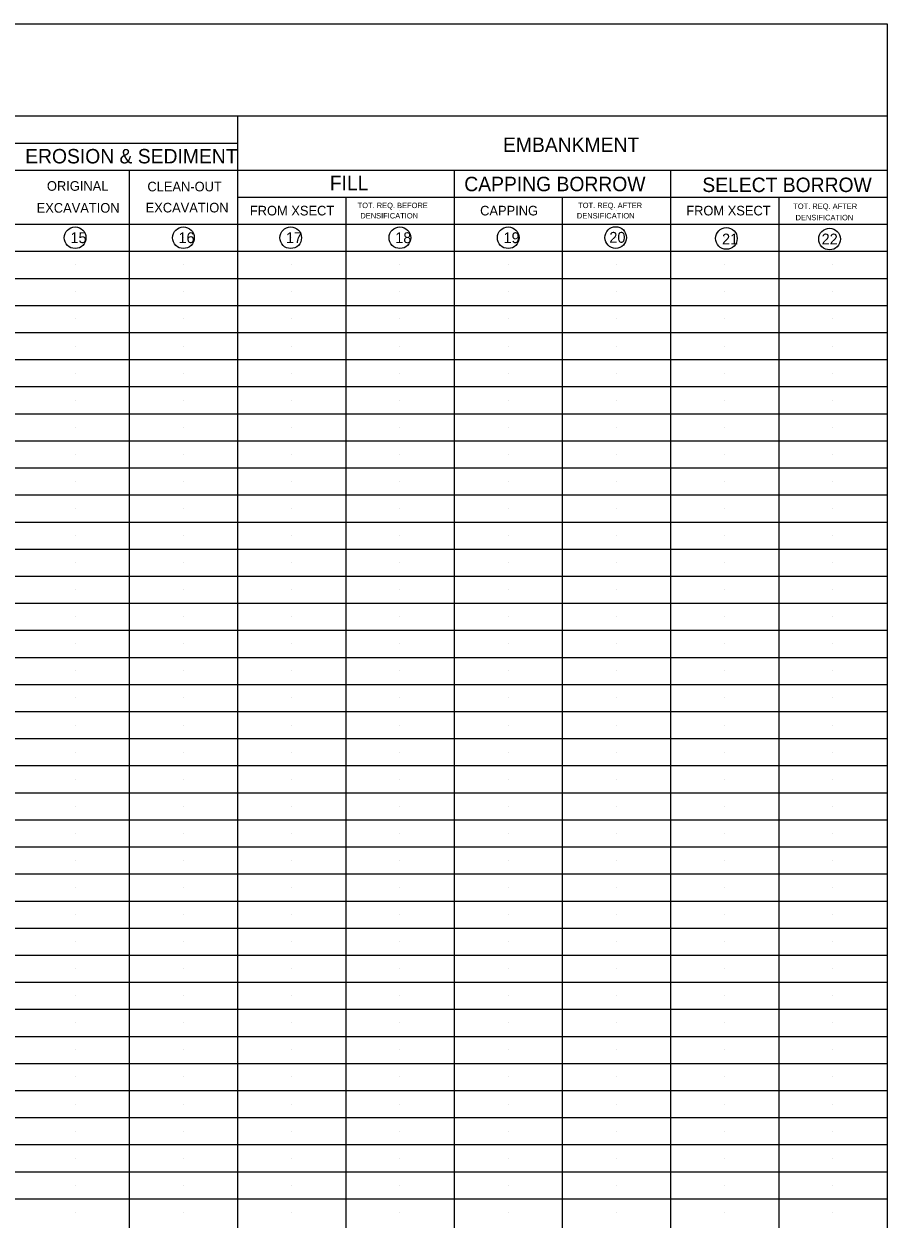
# Model space of a CAD drawing. Extents: x 1.3 to 38.6, y 0 to 21.1.
# Drawn here: x 15.32 to 22.5, y 11.12 to 21.05 of the extents above; entities that cross this region are included whole.
import ezdxf

# ---------------------------------------------------------------- set-up
doc = ezdxf.new("R2010")
doc.units = 0
for name, color, linetype in [('CONS-LOGO', 7, 'Continuous'), ('TTLB-TEXT', 7, 'Continuous'), ('USER-LINE', 7, 'Continuous')]:
    doc.layers.add(name, color=color, linetype=linetype)

msp = doc.modelspace()

# ---------------------------------------------------------------- linework, layer by layer
at = {"layer": 'CONS-LOGO'}
for centre in [(15.7479, 19.278), (16.6479, 19.278), (17.5398, 19.278), (18.4479, 19.278), (19.3479, 19.278), (20.2416, 19.2789), (21.1619, 19.272), (22.02, 19.267)]:
    msp.add_circle(centre, 0.09, dxfattribs=at)
at = {"layer": 'TTLB-TEXT'}
for p, q in [((2.248, 21.055), (22.498, 21.055)), ((22.498, 21.055), (22.498, 1.165)), ((2.248, 20.29), (22.498, 20.29)), ((17.098, 20.2901), (17.098, 4.54)), ((2.698, 20.065), (17.098, 20.065)), ((2.698, 19.84), (22.498, 19.84)), ((16.198, 19.8401), (16.198, 4.54)), ((18.898, 19.84), (18.898, 4.54)), ((20.698, 19.84), (20.698, 4.54)), ((17.098, 19.615), (22.498, 19.615)), ((17.998, 19.6151), (17.998, 4.54)), ((19.798, 19.6151), (19.798, 4.54)), ((21.598, 19.615), (21.598, 1.165)), ((2.698, 19.39), (22.498, 19.39)), ((2.248, 19.165), (22.498, 19.165)), ((2.698, 18.94), (22.498, 18.94)), ((2.698, 18.715), (22.498, 18.715)), ((2.698, 18.49), (22.498, 18.49)), ((2.698, 18.265), (22.498, 18.265)), ((2.698, 18.04), (22.498, 18.04)), ((2.698, 17.815), (22.498, 17.815)), ((2.698, 17.59), (22.498, 17.59)), ((2.698, 17.365), (22.498, 17.365)), ((2.698, 17.14), (22.498, 17.14)), ((2.698, 16.915), (22.498, 16.915)), ((2.698, 16.69), (22.498, 16.69)), ((2.698, 16.465), (22.498, 16.465)), ((2.698, 16.24), (22.498, 16.24)), ((2.698, 16.015), (22.498, 16.015)), ((2.698, 15.79), (22.498, 15.79)), ((2.698, 15.565), (22.498, 15.565)), ((2.698, 15.34), (22.498, 15.34)), ((2.698, 15.115), (22.498, 15.115)), ((2.698, 14.89), (22.498, 14.89)), ((2.698, 14.665), (22.498, 14.665)), ((2.698, 14.44), (22.498, 14.44)), ((2.698, 14.215), (22.498, 14.215)), ((2.698, 13.99), (22.498, 13.99)), ((2.698, 13.765), (22.498, 13.765)), ((2.698, 13.54), (22.498, 13.54)), ((2.698, 13.315), (22.498, 13.315)), ((2.698, 13.09), (22.498, 13.09)), ((2.698, 12.865), (22.498, 12.865)), ((2.698, 12.64), (22.498, 12.64)), ((2.698, 12.415), (22.498, 12.415)), ((2.698, 12.19), (22.498, 12.19)), ((2.698, 11.965), (22.498, 11.965)), ((2.698, 11.74), (22.498, 11.74)), ((2.698, 11.515), (22.498, 11.515)), ((2.698, 11.29), (22.498, 11.29))]:
    msp.add_line(p, q, dxfattribs=at)
at = {"layer": 'USER-LINE'}
for p, q in [((17.548, 19.5025), (17.548, 19.5025)), ((18.448, 19.5025), (18.448, 19.5025)), ((19.348, 19.5025), (19.348, 19.5025)), ((20.248, 19.5025), (20.248, 19.5025)), ((21.148, 19.5025), (21.148, 19.5025)), ((22.048, 19.5025), (22.048, 19.5025)), ((15.748, 19.2775), (15.748, 19.2775)), ((16.648, 19.2775), (16.648, 19.2775)), ((17.548, 19.2775), (17.548, 19.2775)), ((18.448, 19.2775), (18.448, 19.2775)), ((19.348, 19.2775), (19.348, 19.2775)), ((20.248, 19.2775), (20.248, 19.2775)), ((21.148, 19.2775), (21.148, 19.2775)), ((22.048, 19.2775), (22.048, 19.2775)), ((15.748, 19.0525), (15.748, 19.0525)), ((16.648, 19.0525), (16.648, 19.0525)), ((17.548, 19.0525), (17.548, 19.0525)), ((18.448, 19.0525), (18.448, 19.0525)), ((19.348, 19.0525), (19.348, 19.0525)), ((20.248, 19.0525), (20.248, 19.0525)), ((21.148, 19.0525), (21.148, 19.0525)), ((22.048, 19.0525), (22.048, 19.0525)), ((15.748, 18.8275), (15.748, 18.8275)), ((16.648, 18.8275), (16.648, 18.8275)), ((17.548, 18.8275), (17.548, 18.8275)), ((18.448, 18.8275), (18.448, 18.8275)), ((19.348, 18.8275), (19.348, 18.8275)), ((20.248, 18.8275), (20.248, 18.8275)), ((21.148, 18.8275), (21.148, 18.8275)), ((22.048, 18.8275), (22.048, 18.8275)), ((15.748, 18.6025), (15.748, 18.6025)), ((16.648, 18.6025), (16.648, 18.6025)), ((17.548, 18.6025), (17.548, 18.6025)), ((18.448, 18.6025), (18.448, 18.6025)), ((19.348, 18.6025), (19.348, 18.6025)), ((20.248, 18.6025), (20.248, 18.6025)), ((21.148, 18.6025), (21.148, 18.6025)), ((22.048, 18.6025), (22.048, 18.6025)), ((15.748, 18.3775), (15.748, 18.3775)), ((16.648, 18.3775), (16.648, 18.3775)), ((17.548, 18.3775), (17.548, 18.3775)), ((18.448, 18.3775), (18.448, 18.3775)), ((19.348, 18.3775), (19.348, 18.3775)), ((20.248, 18.3775), (20.248, 18.3775)), ((21.148, 18.3775), (21.148, 18.3775)), ((22.048, 18.3775), (22.048, 18.3775)), ((15.748, 18.1525), (15.748, 18.1525)), ((16.648, 18.1525), (16.648, 18.1525)), ((17.548, 18.1525), (17.548, 18.1525)), ((18.448, 18.1525), (18.448, 18.1525)), ((19.348, 18.1525), (19.348, 18.1525)), ((20.248, 18.1525), (20.248, 18.1525)), ((21.148, 18.1525), (21.148, 18.1525)), ((22.048, 18.1525), (22.048, 18.1525)), ((15.748, 17.9275), (15.748, 17.9275)), ((16.648, 17.9275), (16.648, 17.9275)), ((17.548, 17.9275), (17.548, 17.9275)), ((18.448, 17.9275), (18.448, 17.9275)), ((19.348, 17.9275), (19.348, 17.9275)), ((20.248, 17.9275), (20.248, 17.9275)), ((21.148, 17.9275), (21.148, 17.9275)), ((22.048, 17.9275), (22.048, 17.9275)), ((15.748, 17.7025), (15.748, 17.7025)), ((16.648, 17.7025), (16.648, 17.7025)), ((17.548, 17.7025), (17.548, 17.7025)), ((18.448, 17.7025), (18.448, 17.7025)), ((19.348, 17.7025), (19.348, 17.7025)), ((20.248, 17.7025), (20.248, 17.7025)), ((21.148, 17.7025), (21.148, 17.7025)), ((22.048, 17.7025), (22.048, 17.7025)), ((15.748, 17.4775), (15.748, 17.4775)), ((16.648, 17.4775), (16.648, 17.4775)), ((17.548, 17.4775), (17.548, 17.4775)), ((18.448, 17.4775), (18.448, 17.4775)), ((19.348, 17.4775), (19.348, 17.4775)), ((20.248, 17.4775), (20.248, 17.4775)), ((21.148, 17.4775), (21.148, 17.4775)), ((22.048, 17.4775), (22.048, 17.4775)), ((15.748, 17.2525), (15.748, 17.2525)), ((16.648, 17.2525), (16.648, 17.2525)), ((17.548, 17.2525), (17.548, 17.2525)), ((18.448, 17.2525), (18.448, 17.2525)), ((19.348, 17.2525), (19.348, 17.2525)), ((20.248, 17.2525), (20.248, 17.2525)), ((21.148, 17.2525), (21.148, 17.2525)), ((22.048, 17.2525), (22.048, 17.2525)), ((15.748, 17.0275), (15.748, 17.0275)), ((16.648, 17.0275), (16.648, 17.0275)), ((17.548, 17.0275), (17.548, 17.0275)), ((18.448, 17.0275), (18.448, 17.0275)), ((19.348, 17.0275), (19.348, 17.0275)), ((20.248, 17.0275), (20.248, 17.0275)), ((21.148, 17.0275), (21.148, 17.0275)), ((22.048, 17.0275), (22.048, 17.0275)), ((15.748, 16.8025), (15.748, 16.8025)), ((16.648, 16.8025), (16.648, 16.8025)), ((17.548, 16.8025), (17.548, 16.8025)), ((18.448, 16.8025), (18.448, 16.8025)), ((19.348, 16.8025), (19.348, 16.8025)), ((20.248, 16.8025), (20.248, 16.8025)), ((21.148, 16.8025), (21.148, 16.8025)), ((22.048, 16.8025), (22.048, 16.8025)), ((15.748, 16.5775), (15.748, 16.5775)), ((16.648, 16.5775), (16.648, 16.5775)), ((17.548, 16.5775), (17.548, 16.5775)), ((18.448, 16.5775), (18.448, 16.5775)), ((19.348, 16.5775), (19.348, 16.5775)), ((20.248, 16.5775), (20.248, 16.5775)), ((21.148, 16.5775), (21.148, 16.5775)), ((22.048, 16.5775), (22.048, 16.5775)), ((15.748, 16.3525), (15.748, 16.3525)), ((16.648, 16.3525), (16.648, 16.3525)), ((17.548, 16.3525), (17.548, 16.3525)), ((18.448, 16.3525), (18.448, 16.3525)), ((19.348, 16.3525), (19.348, 16.3525)), ((20.248, 16.3525), (20.248, 16.3525)), ((21.148, 16.3525), (21.148, 16.3525)), ((22.048, 16.3525), (22.048, 16.3525)), ((15.748, 16.1275), (15.748, 16.1275)), ((16.648, 16.1275), (16.648, 16.1275)), ((17.548, 16.1275), (17.548, 16.1275)), ((18.448, 16.1275), (18.448, 16.1275)), ((19.348, 16.1275), (19.348, 16.1275)), ((20.248, 16.1275), (20.248, 16.1275)), ((21.148, 16.1275), (21.148, 16.1275)), ((22.048, 16.1275), (22.048, 16.1275)), ((15.748, 15.9025), (15.748, 15.9025)), ((16.648, 15.9025), (16.648, 15.9025)), ((17.548, 15.9025), (17.548, 15.9025)), ((18.448, 15.9025), (18.448, 15.9025)), ((19.348, 15.9025), (19.348, 15.9025)), ((20.248, 15.9025), (20.248, 15.9025)), ((21.148, 15.9025), (21.148, 15.9025)), ((22.048, 15.9025), (22.048, 15.9025)), ((15.748, 15.6775), (15.748, 15.6775)), ((16.648, 15.6775), (16.648, 15.6775)), ((17.548, 15.6775), (17.548, 15.6775)), ((18.448, 15.6775), (18.448, 15.6775)), ((19.348, 15.6775), (19.348, 15.6775)), ((20.248, 15.6775), (20.248, 15.6775)), ((21.148, 15.6775), (21.148, 15.6775)), ((22.048, 15.6775), (22.048, 15.6775)), ((15.748, 15.4525), (15.748, 15.4525)), ((16.648, 15.4525), (16.648, 15.4525)), ((17.548, 15.4525), (17.548, 15.4525)), ((18.448, 15.4525), (18.448, 15.4525)), ((19.348, 15.4525), (19.348, 15.4525)), ((20.248, 15.4525), (20.248, 15.4525)), ((21.148, 15.4525), (21.148, 15.4525)), ((22.048, 15.4525), (22.048, 15.4525)), ((15.748, 15.2275), (15.748, 15.2275)), ((16.648, 15.2275), (16.648, 15.2275)), ((17.548, 15.2275), (17.548, 15.2275)), ((18.448, 15.2275), (18.448, 15.2275)), ((19.348, 15.2275), (19.348, 15.2275)), ((20.248, 15.2275), (20.248, 15.2275)), ((21.148, 15.2275), (21.148, 15.2275)), ((22.048, 15.2275), (22.048, 15.2275)), ((15.748, 15.0025), (15.748, 15.0025)), ((16.648, 15.0025), (16.648, 15.0025)), ((17.548, 15.0025), (17.548, 15.0025)), ((18.448, 15.0025), (18.448, 15.0025)), ((19.348, 15.0025), (19.348, 15.0025)), ((20.248, 15.0025), (20.248, 15.0025)), ((21.148, 15.0025), (21.148, 15.0025)), ((22.048, 15.0025), (22.048, 15.0025)), ((15.748, 14.7775), (15.748, 14.7775)), ((16.648, 14.7775), (16.648, 14.7775)), ((17.548, 14.7775), (17.548, 14.7775)), ((18.448, 14.7775), (18.448, 14.7775)), ((19.348, 14.7775), (19.348, 14.7775)), ((20.248, 14.7775), (20.248, 14.7775)), ((21.148, 14.7775), (21.148, 14.7775)), ((22.048, 14.7775), (22.048, 14.7775)), ((15.748, 14.5525), (15.748, 14.5525)), ((16.648, 14.5525), (16.648, 14.5525)), ((17.548, 14.5525), (17.548, 14.5525)), ((18.448, 14.5525), (18.448, 14.5525)), ((19.348, 14.5525), (19.348, 14.5525)), ((20.248, 14.5525), (20.248, 14.5525)), ((21.148, 14.5525), (21.148, 14.5525)), ((22.048, 14.5525), (22.048, 14.5525)), ((15.748, 14.3275), (15.748, 14.3275)), ((16.648, 14.3275), (16.648, 14.3275)), ((17.548, 14.3275), (17.548, 14.3275)), ((18.448, 14.3275), (18.448, 14.3275)), ((19.348, 14.3275), (19.348, 14.3275)), ((20.248, 14.3275), (20.248, 14.3275)), ((21.148, 14.3275), (21.148, 14.3275)), ((22.048, 14.3275), (22.048, 14.3275)), ((15.748, 14.1025), (15.748, 14.1025)), ((16.648, 14.1025), (16.648, 14.1025)), ((17.548, 14.1025), (17.548, 14.1025)), ((18.448, 14.1025), (18.448, 14.1025)), ((19.348, 14.1025), (19.348, 14.1025)), ((20.248, 14.1025), (20.248, 14.1025)), ((21.148, 14.1025), (21.148, 14.1025)), ((22.048, 14.1025), (22.048, 14.1025)), ((15.748, 13.8775), (15.748, 13.8775)), ((16.648, 13.8775), (16.648, 13.8775)), ((17.548, 13.8775), (17.548, 13.8775)), ((18.448, 13.8775), (18.448, 13.8775)), ((19.348, 13.8775), (19.348, 13.8775)), ((20.248, 13.8775), (20.248, 13.8775)), ((21.148, 13.8775), (21.148, 13.8775)), ((22.048, 13.8775), (22.048, 13.8775)), ((15.748, 13.6525), (15.748, 13.6525)), ((16.648, 13.6525), (16.648, 13.6525)), ((17.548, 13.6525), (17.548, 13.6525)), ((18.448, 13.6525), (18.448, 13.6525)), ((19.348, 13.6525), (19.348, 13.6525)), ((20.248, 13.6525), (20.248, 13.6525)), ((21.148, 13.6525), (21.148, 13.6525)), ((22.048, 13.6525), (22.048, 13.6525)), ((15.748, 13.4275), (15.748, 13.4275)), ((16.648, 13.4275), (16.648, 13.4275)), ((17.548, 13.4275), (17.548, 13.4275)), ((18.448, 13.4275), (18.448, 13.4275)), ((19.348, 13.4275), (19.348, 13.4275)), ((20.248, 13.4275), (20.248, 13.4275)), ((21.148, 13.4275), (21.148, 13.4275)), ((22.048, 13.4275), (22.048, 13.4275)), ((15.748, 13.2025), (15.748, 13.2025)), ((16.648, 13.2025), (16.648, 13.2025)), ((17.548, 13.2025), (17.548, 13.2025)), ((18.448, 13.2025), (18.448, 13.2025)), ((19.348, 13.2025), (19.348, 13.2025)), ((20.248, 13.2025), (20.248, 13.2025)), ((21.148, 13.2025), (21.148, 13.2025)), ((22.048, 13.2025), (22.048, 13.2025)), ((15.748, 12.9775), (15.748, 12.9775)), ((16.648, 12.9775), (16.648, 12.9775)), ((17.548, 12.9775), (17.548, 12.9775)), ((18.448, 12.9775), (18.448, 12.9775)), ((19.348, 12.9775), (19.348, 12.9775)), ((20.248, 12.9775), (20.248, 12.9775)), ((21.148, 12.9775), (21.148, 12.9775)), ((22.048, 12.9775), (22.048, 12.9775)), ((15.748, 12.7525), (15.748, 12.7525)), ((16.648, 12.7525), (16.648, 12.7525)), ((17.548, 12.7525), (17.548, 12.7525)), ((18.448, 12.7525), (18.448, 12.7525)), ((19.348, 12.7525), (19.348, 12.7525)), ((20.248, 12.7525), (20.248, 12.7525)), ((21.148, 12.7525), (21.148, 12.7525)), ((22.048, 12.7525), (22.048, 12.7525)), ((15.748, 12.5275), (15.748, 12.5275)), ((16.648, 12.5275), (16.648, 12.5275)), ((17.548, 12.5275), (17.548, 12.5275)), ((18.448, 12.5275), (18.448, 12.5275)), ((19.348, 12.5275), (19.348, 12.5275)), ((20.248, 12.5275), (20.248, 12.5275)), ((21.148, 12.5275), (21.148, 12.5275)), ((22.048, 12.5275), (22.048, 12.5275)), ((15.748, 12.3025), (15.748, 12.3025)), ((16.648, 12.3025), (16.648, 12.3025)), ((17.548, 12.3025), (17.548, 12.3025)), ((18.448, 12.3025), (18.448, 12.3025)), ((19.348, 12.3025), (19.348, 12.3025)), ((20.248, 12.3025), (20.248, 12.3025)), ((21.148, 12.3025), (21.148, 12.3025)), ((22.048, 12.3025), (22.048, 12.3025)), ((15.748, 12.0775), (15.748, 12.0775)), ((16.648, 12.0775), (16.648, 12.0775)), ((17.548, 12.0775), (17.548, 12.0775)), ((18.448, 12.0775), (18.448, 12.0775)), ((19.348, 12.0775), (19.348, 12.0775)), ((20.248, 12.0775), (20.248, 12.0775)), ((21.148, 12.0775), (21.148, 12.0775)), ((22.048, 12.0775), (22.048, 12.0775)), ((15.748, 11.8525), (15.748, 11.8525)), ((16.648, 11.8525), (16.648, 11.8525)), ((17.548, 11.8525), (17.548, 11.8525)), ((18.448, 11.8525), (18.448, 11.8525)), ((19.348, 11.8525), (19.348, 11.8525)), ((20.248, 11.8525), (20.248, 11.8525)), ((21.148, 11.8525), (21.148, 11.8525)), ((22.048, 11.8525), (22.048, 11.8525)), ((15.748, 11.6275), (15.748, 11.6275)), ((16.648, 11.6275), (16.648, 11.6275)), ((17.548, 11.6275), (17.548, 11.6275)), ((18.448, 11.6275), (18.448, 11.6275)), ((19.348, 11.6275), (19.348, 11.6275)), ((20.248, 11.6275), (20.248, 11.6275)), ((21.148, 11.6275), (21.148, 11.6275)), ((22.048, 11.6275), (22.048, 11.6275)), ((15.748, 11.4025), (15.748, 11.4025)), ((16.648, 11.4025), (16.648, 11.4025)), ((17.548, 11.4025), (17.548, 11.4025)), ((18.448, 11.4025), (18.448, 11.4025)), ((19.348, 11.4025), (19.348, 11.4025)), ((20.248, 11.4025), (20.248, 11.4025)), ((21.148, 11.4025), (21.148, 11.4025)), ((22.048, 11.4025), (22.048, 11.4025)), ((15.748, 11.1775), (15.748, 11.1775)), ((16.648, 11.1775), (16.648, 11.1775)), ((17.548, 11.1775), (17.548, 11.1775)), ((18.448, 11.1775), (18.448, 11.1775)), ((19.348, 11.1775), (19.348, 11.1775)), ((20.248, 11.1775), (20.248, 11.1775)), ((21.148, 11.1775), (21.148, 11.1775)), ((22.048, 11.1775), (22.048, 11.1775))]:
    msp.add_line(p, q, dxfattribs=at)

# ---------------------------------------------------------------- texts
at = {"layer": 'CONS-LOGO'}
for s, height, p in [('EMBANKMENT', 0.12, (19.3051, 19.9905)), ('EROSION & SEDIMENT', 0.12, (15.3324, 19.8955)), ('FILL', 0.12, (17.8648, 19.6725)), ('CAPPING BORROW', 0.12, (18.9828, 19.6645)), ('SELECT BORROW', 0.12, (20.9618, 19.6575)), ('ORIGINAL', 0.08, (15.5131, 19.668)), ('CLEAN-OUT', 0.08, (16.3487, 19.663)), ('TOT. REQ. BEFORE', 0.044994, (18.0964, 19.524)), ('TOT. REQ. AFTER', 0.045, (19.9297, 19.524)), ('EXCAVATION', 0.08, (15.4279, 19.486)), ('EXCAVATION', 0.08, (16.3339, 19.488)), ('FROM XSECT', 0.08, (17.2003, 19.463)), ('DENSIFICATION', 0.044994, (18.1189, 19.438)), ('CAPPING', 0.08, (19.1146, 19.463)), ('DENSIFICATION', 0.044994, (19.9189, 19.438)), ('FROM XSECT', 0.08, (20.8283, 19.463)), ('TOT. REQ. AFTER', 0.045, (21.7177, 19.517)), ('DENSIFICATION', 0.044994, (21.7369, 19.423)), ('15', 0.09, (15.709, 19.233)), ('16', 0.09, (16.607, 19.233)), ('17', 0.09, (17.501, 19.233)), ('18', 0.09, (18.409, 19.233)), ('19', 0.09, (19.309, 19.233)), ('20', 0.09, (20.189, 19.236)), ('21', 0.09, (21.126, 19.222)), ('22', 0.09, (21.954, 19.222))]:
    msp.add_text(s, height=height, dxfattribs=at).set_placement(p)

doc.saveas('drawing.dxf')
